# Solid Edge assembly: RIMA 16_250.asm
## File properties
Title: Zylinder
Author: ahadarics
Template: iso metric assembly.asm
Last saved by: ahadarics
Revision: 25
Application: Solid Edge
Username: ahadarics
Dokumentum tartalom típus: 1
Document Number: RIMA 16/250
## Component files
Profilrohr.par
Kolbenstange.par
Kit_1.par
Kit_2.par
Mutter_1.par
Mutter_2.par
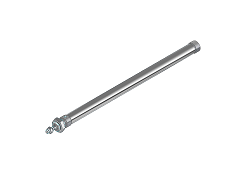
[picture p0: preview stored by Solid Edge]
